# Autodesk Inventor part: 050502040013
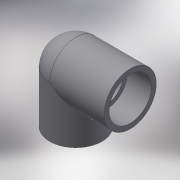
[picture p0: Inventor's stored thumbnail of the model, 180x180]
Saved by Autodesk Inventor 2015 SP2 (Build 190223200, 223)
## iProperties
Created: 2017-10
Part Number: 050502040013
Material: Generic
Description: PLASSON 90° ELBOW THR-CEM PVC 40-1.1/4"
Document SubType Name: Modeling
Designer: KIM
Density: 1 g/cm^3
Appearance: Default
Author: KIM
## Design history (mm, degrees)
derived "050502.ipt"
feature "Solid1::050502.ipt"
tag "TaggingFeature1"
workaxis "Work Axis3"
body "Solid1"
other parameters: "d1" = 48, "d3" = 47, "d4" = 48, "d6" = 90 deg, "d7" = 38.952, "d8" = 22, "d9" = 0, "d11" = 26, "d12" = 0, "d14" = 31.1616, "d16" = 19.476, "d17" = 0, "d18" = 0, "G_" = 38.952, "E_" = 48, "l_" = 26, "lt_" = 22, "Z_" = 21, "H_" = 74
